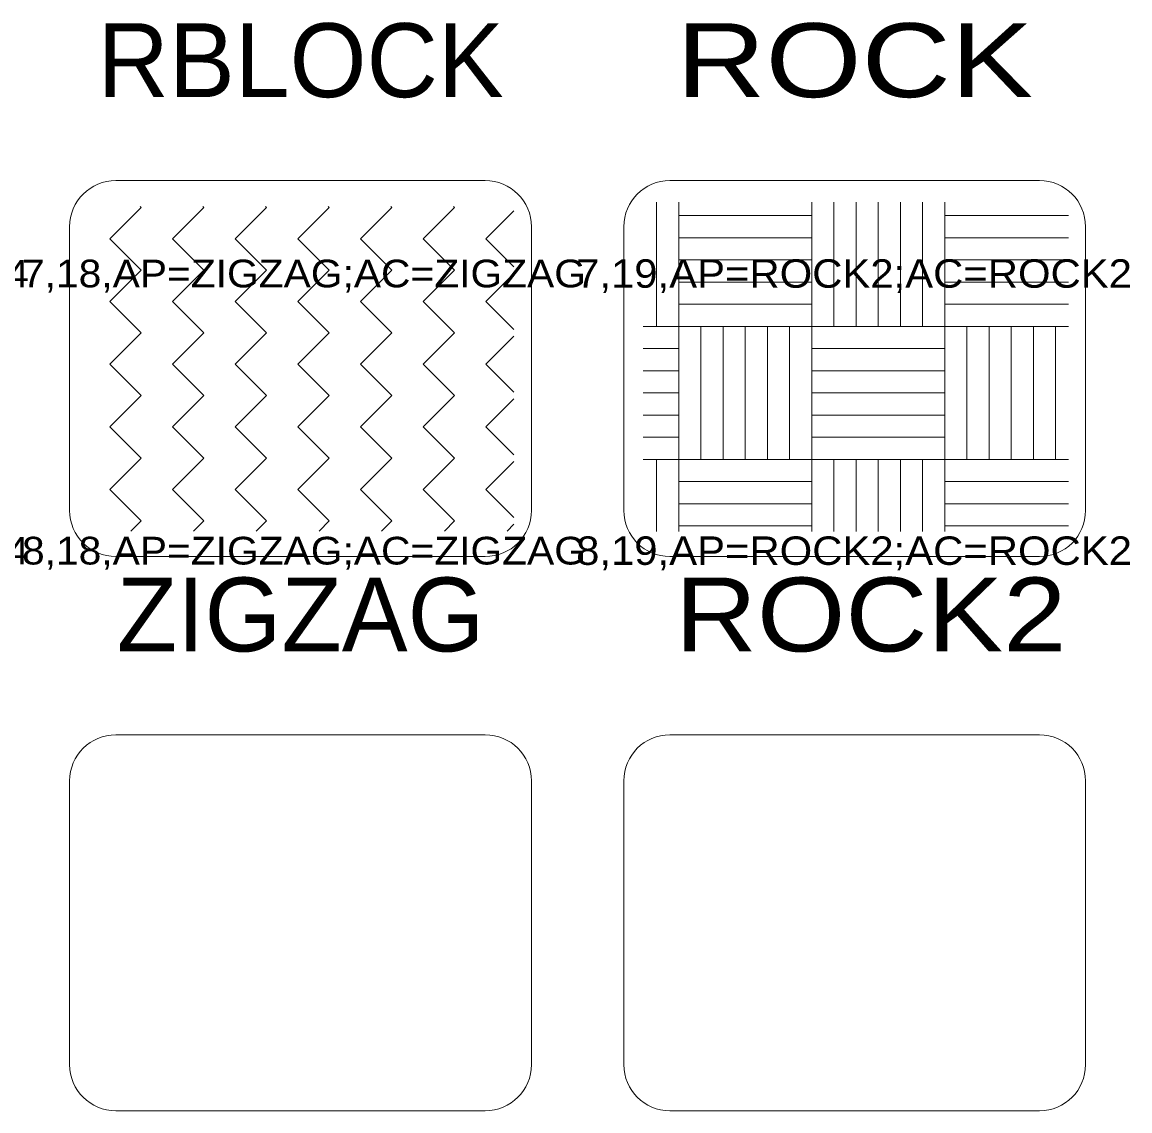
# Model space of a CAD drawing. Extents: x 95935 to 95946.4, y 95971.2 to 95974.7.
# Drawn here: x 95945.234 to 95946.434, y 95971.925 to 95973.103 of the extents above; entities that cross this region are included whole.
import ezdxf
from ezdxf.enums import TextEntityAlignment as Align

# ---------------------------------------------------------------- set-up
doc = ezdxf.new("R2010")
doc.units = 0
doc.header["$LTSCALE"] = 0.013
for name, color, linetype, lineweight in [('1', 7, 'Continuous', 13), ('6', 7, 'Continuous', 13), ('63', 7, 'Continuous', 13)]:
    doc.layers.add(name, color=color, linetype=linetype, lineweight=lineweight)
doc.layers.add('20', color=7, linetype='Continuous')

msp = doc.modelspace()

# ---------------------------------------------------------------- linework, layer by layer
at = {"layer": '1'}
for p, q in [((95945.3357, 95972.9318), (95945.7357, 95972.9318)), ((95945.9357, 95972.9318), (95946.3357, 95972.9318)), ((95945.2857, 95972.5747), (95945.2857, 95972.8818)), ((95945.7857, 95972.8818), (95945.7857, 95972.5747)), ((95945.8857, 95972.5747), (95945.8857, 95972.8818)), ((95946.3857, 95972.8818), (95946.3857, 95972.5747)), ((95945.7357, 95972.5247), (95945.3357, 95972.5247)), ((95946.3357, 95972.5247), (95945.9357, 95972.5247)), ((95945.3357, 95972.3318), (95945.7357, 95972.3318)), ((95945.9357, 95972.3318), (95946.3357, 95972.3318)), ((95945.2857, 95971.9747), (95945.2857, 95972.2818)), ((95945.7857, 95972.2818), (95945.7857, 95971.9747)), ((95945.8857, 95971.9747), (95945.8857, 95972.2818)), ((95946.3857, 95972.2818), (95946.3857, 95971.9747)), ((95945.7357, 95971.9247), (95945.3357, 95971.9247)), ((95946.3357, 95971.9247), (95945.9357, 95971.9247))]:
    msp.add_line(p, q, dxfattribs=at)
for centre, start, end in [((95945.3357, 95972.8818), 90, 180), ((95945.7357, 95972.8818), 0, 90), ((95945.9357, 95972.8818), 90, 180), ((95946.3357, 95972.8818), 0, 90), ((95945.3357, 95972.5747), 180, 270), ((95945.7357, 95972.5747), 270, 0), ((95945.9357, 95972.5747), 180, 270), ((95946.3357, 95972.5747), 270, 0), ((95945.3357, 95972.2818), 90, 180), ((95945.7357, 95972.2818), 0, 90), ((95945.9357, 95972.2818), 90, 180), ((95946.3357, 95972.2818), 0, 90), ((95945.3357, 95971.9747), 180, 270), ((95945.7357, 95971.9747), 270, 0), ((95945.9357, 95971.9747), 180, 270), ((95946.3357, 95971.9747), 270, 0)]:
    msp.add_arc(centre, 0.05, start, end, dxfattribs=at)
at = {"layer": '6'}
for p, q in [((95945.397, 95972.8688), (95945.4309, 95972.9027)), ((95945.4309, 95972.9027), (95945.4298, 95972.9038)), ((95945.5327, 95972.8688), (95945.5667, 95972.9027)), ((95945.5667, 95972.9027), (95945.5656, 95972.9038)), ((95945.6685, 95972.8688), (95945.7024, 95972.9027)), ((95945.7024, 95972.9027), (95945.7013, 95972.9038)), ((95945.9212, 95972.7739), (95945.9212, 95972.9082)), ((95945.9452, 95972.9082), (95945.9452, 95972.5517)), ((95946.0892, 95972.9082), (95946.0892, 95972.5517)), ((95946.1132, 95972.7739), (95946.1132, 95972.9082)), ((95946.1372, 95972.7739), (95946.1372, 95972.9082)), ((95946.1612, 95972.7739), (95946.1612, 95972.9082)), ((95946.1852, 95972.7739), (95946.1852, 95972.9082)), ((95946.2092, 95972.7739), (95946.2092, 95972.9082)), ((95946.2332, 95972.9082), (95946.2332, 95972.5517)), ((95945.9452, 95972.8939), (95946.0172, 95972.8939)), ((95946.0172, 95972.8939), (95946.0892, 95972.8939)), ((95946.2332, 95972.8939), (95946.3052, 95972.8939)), ((95946.3052, 95972.8939), (95946.3672, 95972.8939)), ((95945.9452, 95972.8699), (95946.0172, 95972.8699)), ((95946.0172, 95972.8699), (95946.0892, 95972.8699)), ((95946.2332, 95972.8699), (95946.3052, 95972.8699)), ((95946.3052, 95972.8699), (95946.3672, 95972.8699)), ((95945.9452, 95972.8459), (95946.0172, 95972.8459)), ((95946.0172, 95972.8459), (95946.0892, 95972.8459)), ((95946.2332, 95972.8459), (95946.3052, 95972.8459)), ((95946.3052, 95972.8459), (95946.3672, 95972.8459)), ((95945.7364, 95972.8009), (95945.7667, 95972.8312)), ((95945.9452, 95972.8219), (95946.0172, 95972.8219)), ((95946.0172, 95972.8219), (95946.0892, 95972.8219)), ((95946.2332, 95972.8219), (95946.3052, 95972.8219)), ((95946.3052, 95972.8219), (95946.3672, 95972.8219)), ((95945.7667, 95972.7706), (95945.7364, 95972.8009)), ((95945.9452, 95972.7979), (95946.0172, 95972.7979)), ((95946.0172, 95972.7979), (95946.0892, 95972.7979)), ((95946.2332, 95972.7979), (95946.3052, 95972.7979)), ((95946.3052, 95972.7979), (95946.3672, 95972.7979)), ((95945.9066, 95972.7739), (95946.3672, 95972.7739)), ((95945.9692, 95972.7019), (95945.9692, 95972.7739)), ((95945.9932, 95972.7019), (95945.9932, 95972.7739)), ((95946.0172, 95972.7019), (95946.0172, 95972.7739)), ((95946.0412, 95972.7019), (95946.0412, 95972.7739)), ((95946.0652, 95972.7019), (95946.0652, 95972.7739)), ((95946.2572, 95972.7019), (95946.2572, 95972.7739)), ((95946.2812, 95972.7019), (95946.2812, 95972.7739)), ((95946.3052, 95972.7019), (95946.3052, 95972.7739)), ((95946.3532, 95972.7019), (95946.3532, 95972.7739)), ((95945.9066, 95972.7499), (95945.9452, 95972.7499)), ((95946.0892, 95972.7499), (95946.2332, 95972.7499)), ((95945.9066, 95972.7259), (95945.9452, 95972.7259)), ((95946.0892, 95972.7259), (95946.2332, 95972.7259)), ((95945.7364, 95972.6651), (95945.7667, 95972.6955)), ((95945.9066, 95972.7019), (95945.9452, 95972.7019)), ((95945.9692, 95972.6299), (95945.9692, 95972.7019)), ((95945.9932, 95972.6299), (95945.9932, 95972.7019)), ((95946.0172, 95972.6299), (95946.0172, 95972.7019)), ((95946.0412, 95972.6299), (95946.0412, 95972.7019)), ((95946.0652, 95972.6299), (95946.0652, 95972.7019)), ((95946.0892, 95972.7019), (95946.2332, 95972.7019)), ((95946.2572, 95972.6299), (95946.2572, 95972.7019)), ((95946.2812, 95972.6299), (95946.2812, 95972.7019)), ((95946.3052, 95972.6299), (95946.3052, 95972.7019)), ((95946.3532, 95972.6299), (95946.3532, 95972.7019)), ((95945.9066, 95972.6779), (95945.9452, 95972.6779)), ((95946.0892, 95972.6779), (95946.2332, 95972.6779)), ((95945.7667, 95972.6348), (95945.7364, 95972.6651)), ((95945.9066, 95972.6539), (95945.9452, 95972.6539)), ((95946.0892, 95972.6539), (95946.2332, 95972.6539)), ((95945.9066, 95972.6299), (95946.3672, 95972.6299)), ((95945.9212, 95972.5517), (95945.9212, 95972.6299)), ((95946.1132, 95972.5517), (95946.1132, 95972.6299)), ((95946.1372, 95972.5517), (95946.1372, 95972.6299)), ((95946.1612, 95972.5517), (95946.1612, 95972.6299)), ((95946.1852, 95972.5517), (95946.1852, 95972.6299)), ((95946.2092, 95972.5517), (95946.2092, 95972.6299)), ((95945.363, 95972.5633), (95945.3291, 95972.5973)), ((95945.4988, 95972.5633), (95945.4648, 95972.5973)), ((95945.6345, 95972.5633), (95945.6006, 95972.5973)), ((95945.9452, 95972.6059), (95946.0172, 95972.6059)), ((95946.0172, 95972.6059), (95946.0892, 95972.6059)), ((95946.2332, 95972.6059), (95946.3052, 95972.6059)), ((95946.3052, 95972.6059), (95946.3672, 95972.6059)), ((95945.9452, 95972.5819), (95946.0172, 95972.5819)), ((95946.0172, 95972.5819), (95946.0892, 95972.5819)), ((95946.2332, 95972.5819), (95946.3052, 95972.5819)), ((95946.3052, 95972.5819), (95946.3672, 95972.5819)), ((95945.352, 95972.5523), (95945.363, 95972.5633)), ((95945.4878, 95972.5523), (95945.4988, 95972.5633)), ((95945.6235, 95972.5523), (95945.6345, 95972.5633)), ((95945.7593, 95972.5523), (95945.7667, 95972.5597)), ((95945.9452, 95972.5579), (95946.0172, 95972.5579)), ((95946.0172, 95972.5579), (95946.0892, 95972.5579)), ((95946.2332, 95972.5579), (95946.3052, 95972.5579)), ((95946.3052, 95972.5579), (95946.3672, 95972.5579))]:
    msp.add_line(p, q, dxfattribs=at)
for points in [[(95945.3291, 95972.8688), (95945.363, 95972.9027), (95945.3619, 95972.9038)], [(95945.4648, 95972.8688), (95945.4988, 95972.9027), (95945.4977, 95972.9038)], [(95945.6006, 95972.8688), (95945.6345, 95972.9027), (95945.6334, 95972.9038)], [(95945.7667, 95972.8384), (95945.7364, 95972.8688), (95945.7667, 95972.8991)], [(95945.3291, 95972.8009), (95945.363, 95972.8348), (95945.3291, 95972.8688)], [(95945.397, 95972.8009), (95945.4309, 95972.8348), (95945.397, 95972.8688)], [(95945.4648, 95972.8009), (95945.4988, 95972.8348), (95945.4648, 95972.8688)], [(95945.5327, 95972.8009), (95945.5667, 95972.8348), (95945.5327, 95972.8688)], [(95945.6006, 95972.8009), (95945.6345, 95972.8348), (95945.6006, 95972.8688)], [(95945.6685, 95972.8009), (95945.7024, 95972.8348), (95945.6685, 95972.8688)], [(95945.3291, 95972.733), (95945.363, 95972.767), (95945.3291, 95972.8009)], [(95945.397, 95972.733), (95945.4309, 95972.767), (95945.397, 95972.8009)], [(95945.4648, 95972.733), (95945.4988, 95972.767), (95945.4648, 95972.8009)], [(95945.5327, 95972.733), (95945.5667, 95972.767), (95945.5327, 95972.8009)], [(95945.6006, 95972.733), (95945.6345, 95972.767), (95945.6006, 95972.8009)], [(95945.6685, 95972.733), (95945.7024, 95972.767), (95945.6685, 95972.8009)], [(95946.3292, 95972.6299), (95946.3292, 95972.7019), (95946.3292, 95972.7739)], [(95945.7667, 95972.7027), (95945.7364, 95972.733), (95945.7667, 95972.7634)], [(95945.3291, 95972.6651), (95945.363, 95972.6991), (95945.3291, 95972.733)], [(95945.397, 95972.6651), (95945.4309, 95972.6991), (95945.397, 95972.733)], [(95945.4648, 95972.6651), (95945.4988, 95972.6991), (95945.4648, 95972.733)], [(95945.5327, 95972.6651), (95945.5667, 95972.6991), (95945.5327, 95972.733)], [(95945.6006, 95972.6651), (95945.6345, 95972.6991), (95945.6006, 95972.733)], [(95945.6685, 95972.6651), (95945.7024, 95972.6991), (95945.6685, 95972.733)], [(95945.3291, 95972.5973), (95945.363, 95972.6312), (95945.3291, 95972.6651)], [(95945.397, 95972.5973), (95945.4309, 95972.6312), (95945.397, 95972.6651)], [(95945.4648, 95972.5973), (95945.4988, 95972.6312), (95945.4648, 95972.6651)], [(95945.5327, 95972.5973), (95945.5667, 95972.6312), (95945.5327, 95972.6651)], [(95945.6006, 95972.5973), (95945.6345, 95972.6312), (95945.6006, 95972.6651)], [(95945.6685, 95972.5973), (95945.7024, 95972.6312), (95945.6685, 95972.6651)], [(95945.7667, 95972.5669), (95945.7364, 95972.5973), (95945.7667, 95972.6276)], [(95945.4199, 95972.5523), (95945.4309, 95972.5633), (95945.397, 95972.5973)], [(95945.5557, 95972.5523), (95945.5667, 95972.5633), (95945.5327, 95972.5973)], [(95945.6914, 95972.5523), (95945.7024, 95972.5633), (95945.6685, 95972.5973)]]:
    msp.add_lwpolyline(points, dxfattribs=at)

# ---------------------------------------------------------------- texts
at = {"layer": '20'}
for s, p in [('RBLOCK', (95945.5358, 95973.022)), ('ZIGZAG', (95945.5358, 95972.422))]:
    msp.add_text(s, height=0.08, dxfattribs=at).set_placement(p, align=Align.CENTER)
for s, width, p in [(' ROCK ', 1.25, (95946.1358, 95973.022)), (' ROCK2', 1.15, (95946.1359, 95972.422))]:
    msp.add_text(s, height=0.08, dxfattribs=dict(at, width=width)).set_placement(p, align=Align.CENTER)
at = {"layer": '63', "width": 1.1}
for s, height, p in [('7,17,AP=WOOD4;AC=WOOD4', 0.0296, (95944.6341, 95972.8163)), ('7,18,AP=ZIGZAG;AC=ZIGZAG', 0.03, (95945.2341, 95972.8161)), ('7,19,AP=ROCK2;AC=ROCK2', 0.0308, (95945.8341, 95972.8157)), ('8,17,AP=WOOD4;AC=WOOD4', 0.0296, (95944.6341, 95972.5163)), ('8,18,AP=ZIGZAG;AC=ZIGZAG', 0.03, (95945.2341, 95972.5161)), ('8,19,AP=ROCK2;AC=ROCK2', 0.0308, (95945.8341, 95972.5157))]:
    msp.add_text(s, height=height, dxfattribs=at).set_placement(p)

doc.saveas('drawing.dxf')
